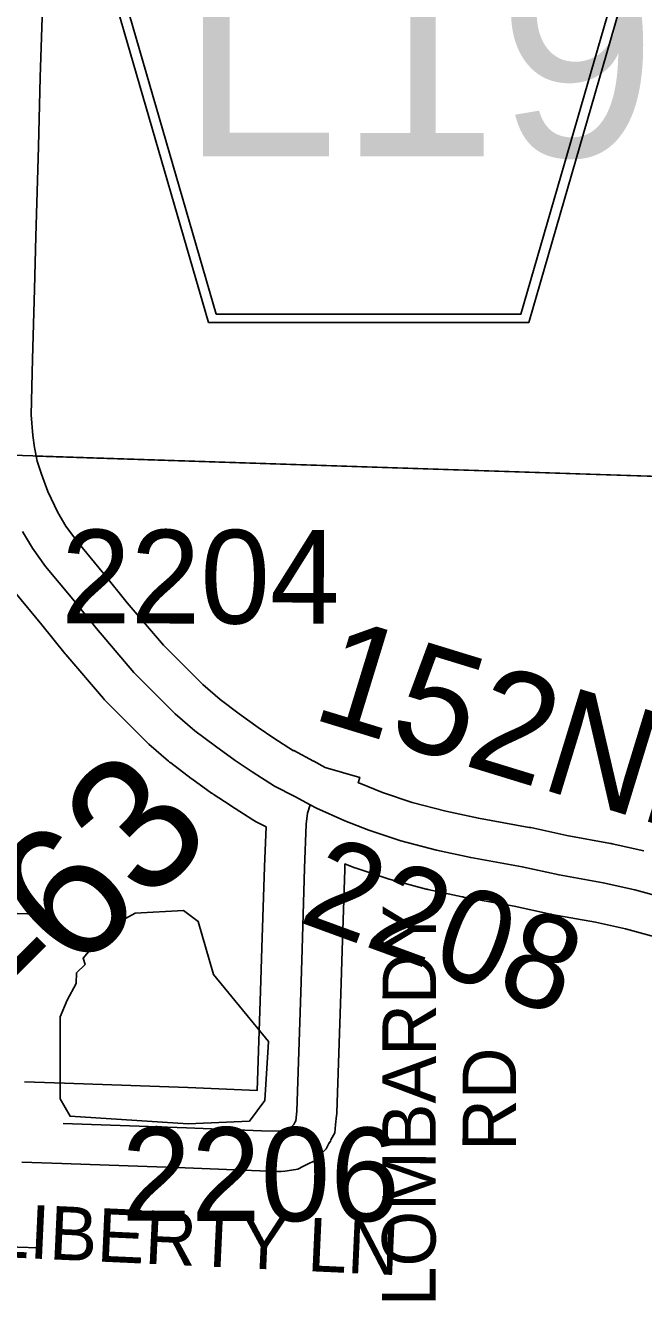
# Model space of a CAD drawing. Extents: x -132.8 to -73.3, y -60 to -26.
# Drawn here: x -124.572 to -124.11, y -41.902 to -40.948 of the extents above; entities that cross this region are included whole.
import ezdxf

# ---------------------------------------------------------------- set-up
doc = ezdxf.new("R2010")
doc.units = 0
for name, color, linetype in [('tdCoHydroRiver', 7, 'Continuous'), ('tdCoRRCL', 7, 'Continuous'), ('tdCoSecRdNmbr', 7, 'Continuous'), ('tdCoSecRdTxt', 7, 'Continuous'), ('tdCoSecRteBand', 7, 'Continuous'), ('tdCoSecRteCL', 7, 'Continuous'), ('tdCoSectLine', 7, 'Continuous'), ('tdCoSectLinePart', 7, 'Continuous'), ('tdCoShieldCoRte', 7, 'Continuous'), ('tdCoSurfEarth', 7, 'Continuous'), ('tdCoSurfGravel', 7, 'Continuous'), ('tdStHwyIntRefPost1', 7, 'Continuous')]:
    doc.layers.add(name, color=color, linetype=linetype)

msp = doc.modelspace()

# ---------------------------------------------------------------- linework, layer by layer
at = {"layer": 'tdCoHydroRiver'}
msp.add_lwpolyline([(-124.45016, -41.76951), (-124.53839, -41.76384), (-124.54591, -41.751), (-124.54574, -41.68948), (-124.54065, -41.677), (-124.53399, -41.66457), (-124.53376, -41.65669), (-124.52727, -41.65056), (-124.52871, -41.64579), (-124.50912, -41.62268), (-124.48988, -41.61219), (-124.45352, -41.61007), (-124.44271, -41.61827), (-124.43121, -41.65804), (-124.39002, -41.70812), (-124.39285, -41.75221), (-124.40434, -41.76766), (-124.45016, -41.76951)], dxfattribs=at)
at = {"layer": 'tdCoRRCL'}
for p, q in [((-124.63015, -41.61051), (-124.5552, -41.61314)), ((-124.63668, -41.8601), (-124.56171, -41.86228))]:
    msp.add_line(p, q, dxfattribs=at)
at = {"layer": 'tdCoSecRteBand'}
for points in [[(-124.55888, -40.92716), (-124.56075, -40.98745), (-124.56195, -41.03885), (-124.56195, -41.03897), (-124.56195, -41.03909), (-124.56405, -41.1063), (-124.56507, -41.14565), (-124.56507, -41.14568), (-124.56507, -41.14571), (-124.56651, -41.1979), (-124.56747, -41.23951), (-124.56632, -41.25503), (-124.56504, -41.26406), (-124.56305, -41.27412), (-124.55975, -41.28384), (-124.5551, -41.2969), (-124.54764, -41.31245), (-124.54155, -41.32268), (-124.53298, -41.33454), (-124.51327, -41.35831), (-124.51315, -41.35846), (-124.51302, -41.35862), (-124.49566, -41.38014), (-124.46868, -41.41178), (-124.43928, -41.44109), (-124.42626, -41.45244), (-124.412, -41.46313), (-124.39789, -41.47336), (-124.38601, -41.48119), (-124.37125, -41.49062), (-124.37116, -41.49045), (-124.35644, -41.49838), (-124.35644, -41.49838), (-124.35622, -41.4985), (-124.34756, -41.50317), (-124.3218, -41.51063), (-124.32294, -41.51456), (-124.32137, -41.51524), (-124.30482, -41.5218), (-124.28258, -41.52923), (-124.25753, -41.53581), (-124.23302, -41.54109), (-124.19504, -41.54794), (-124.19451, -41.54804), (-124.19398, -41.54815), (-124.16686, -41.55405), (-124.13433, -41.55994), (-124.13372, -41.56005), (-124.13312, -41.56018), (-124.10944, -41.56547)], [(-124.57249, -41.73823), (-124.5425, -41.73927), (-124.45027, -41.74248), (-124.4502, -41.74248), (-124.45013, -41.74248), (-124.39845, -41.74453), (-124.39597, -41.67037), (-124.39494, -41.63796), (-124.39301, -41.57742), (-124.39301, -41.57734), (-124.39301, -41.57725), (-124.39189, -41.54759), (-124.39931, -41.54375), (-124.40053, -41.54312), (-124.40168, -41.54238), (-124.4185, -41.53163), (-124.41867, -41.53152), (-124.41884, -41.53141), (-124.43146, -41.5231), (-124.43202, -41.52273), (-124.43256, -41.52233), (-124.44741, -41.51157), (-124.4476, -41.51143), (-124.44779, -41.51129), (-124.46313, -41.49979), (-124.46402, -41.49912), (-124.46485, -41.4984), (-124.47946, -41.48566), (-124.48022, -41.485), (-124.48093, -41.48429), (-124.51191, -41.45341), (-124.51277, -41.45255), (-124.51355, -41.45163), (-124.54158, -41.41876), (-124.54185, -41.41844), (-124.5421, -41.41813), (-124.55959, -41.39645), (-124.5798, -41.37207)], [(-124.10109, -41.62973), (-124.1231, -41.6239), (-124.14561, -41.61887), (-124.17807, -41.613), (-124.17858, -41.6129), (-124.1791, -41.61279), (-124.20621, -41.60689), (-124.24416, -41.60005), (-124.24466, -41.59996), (-124.24516, -41.59986), (-124.27082, -41.59433), (-124.27148, -41.59419), (-124.27212, -41.59402), (-124.29878, -41.58701), (-124.29973, -41.58676), (-124.30066, -41.58645), (-124.32461, -41.57845), (-124.3254, -41.57819), (-124.32616, -41.57788), (-124.33289, -41.57522), (-124.33305, -41.57942), (-124.33497, -41.63987), (-124.336, -41.6723), (-124.336, -41.67233), (-124.33601, -41.67235), (-124.33897, -41.76113), (-124.339, -41.76217), (-124.33911, -41.76322), (-124.33985, -41.77037), (-124.34047, -41.77636), (-124.34335, -41.78165), (-124.34377, -41.78241), (-124.34483, -41.78436), (-124.3469, -41.78815), (-124.34995, -41.79121), (-124.35267, -41.79392), (-124.35611, -41.79736), (-124.36046, -41.79954), (-124.36392, -41.80126), (-124.36817, -41.80339), (-124.37288, -41.8041), (-124.37781, -41.80484), (-124.38059, -41.80526), (-124.3834, -41.80515), (-124.39647, -41.80466), (-124.3965, -41.80466), (-124.39652, -41.80465), (-124.45243, -41.80244), (-124.54459, -41.79923), (-124.57457, -41.79819)]]:
    msp.add_lwpolyline(points, dxfattribs=at)
at = {"layer": 'tdCoSecRteCL'}
for points in [[(-124.35897, -41.53109), (-124.37045, -41.52491), (-124.38552, -41.51711), (-124.40234, -41.50636), (-124.41495, -41.49804), (-124.4298, -41.48728), (-124.44514, -41.47578), (-124.45975, -41.46305), (-124.49072, -41.43216), (-124.51875, -41.39929), (-124.53637, -41.37745), (-124.55671, -41.35292), (-124.56664, -41.33917), (-124.5741, -41.32664)], [(-124.54355, -41.76925), (-124.45132, -41.77246), (-124.39534, -41.77468), (-124.38227, -41.77517), (-124.37733, -41.77443), (-124.37388, -41.77271), (-124.37117, -41.76999), (-124.37011, -41.76805), (-124.36969, -41.76728), (-124.36895, -41.76013), (-124.36599, -41.67135), (-124.36496, -41.63892), (-124.36303, -41.57838), (-124.3618, -41.54558), (-124.36081, -41.53744), (-124.35897, -41.53109)], [(-124.09229, -41.60103), (-124.11598, -41.59475), (-124.13967, -41.58946), (-124.17272, -41.58348), (-124.20036, -41.57747), (-124.23884, -41.57053), (-124.2645, -41.565), (-124.29116, -41.558), (-124.31511, -41.55), (-124.33289, -41.54295), (-124.35413, -41.5337), (-124.35897, -41.53109)]]:
    msp.add_lwpolyline(points, dxfattribs=at)
at = {"layer": 'tdCoSectLine'}
msp.add_lwpolyline([(-124.61958, -41.26852), (-123.619, -41.30129)], dxfattribs=at)
at = {"layer": 'tdCoSectLinePart'}
msp.add_lwpolyline([(-124.56409, -41.27033), (-123.619, -41.30129)], dxfattribs=at)
at = {"layer": 'tdCoShieldCoRte'}
for points in [[(-124.43497, -41.17057), (-124.51691, -40.88768), (-124.52079, -40.87452), (-124.52151, -40.86864), (-124.52151, -40.86081), (-124.51727, -40.8505), (-124.51, -40.84201), (-124.50042, -40.83534), (-124.33315, -40.763), (-124.32563, -40.76136), (-124.31521, -40.76045), (-124.30478, -40.76136), (-124.29727, -40.763), (-124.12999, -40.83534), (-124.12041, -40.84201), (-124.11314, -40.8505), (-124.1089, -40.86081), (-124.1089, -40.86864), (-124.10963, -40.87452), (-124.1135, -40.88768), (-124.19545, -41.17057)], [(-124.42911, -41.16424), (-124.50884, -40.88897), (-124.51256, -40.87634), (-124.51326, -40.87069), (-124.51326, -40.86318), (-124.50919, -40.85328), (-124.50221, -40.84513), (-124.49301, -40.83873), (-124.33243, -40.76927), (-124.32521, -40.7677), (-124.31521, -40.76683), (-124.3052, -40.7677), (-124.29798, -40.76927), (-124.1374, -40.83873), (-124.1282, -40.84513), (-124.12122, -40.85328), (-124.11715, -40.86318), (-124.11715, -40.87069), (-124.11785, -40.87634), (-124.12157, -40.88897), (-124.20131, -41.16424)]]:
    msp.add_lwpolyline(points, close=True, dxfattribs=at)
at = {"layer": 'tdCoSurfEarth'}
msp.add_lwpolyline([(-124.54355, -41.76925), (-124.45132, -41.77246), (-124.39534, -41.77468), (-124.38227, -41.77517), (-124.37733, -41.77443), (-124.37388, -41.77271), (-124.37117, -41.76999), (-124.37011, -41.76805), (-124.36969, -41.76728), (-124.36895, -41.76013), (-124.36599, -41.67135), (-124.36496, -41.63892)], dxfattribs=at)
at = {"layer": 'tdCoSurfGravel'}
for points in [[(-124.09229, -41.60103), (-124.11598, -41.59475), (-124.13967, -41.58946), (-124.17272, -41.58348), (-124.20036, -41.57747), (-124.23884, -41.57053), (-124.2645, -41.565), (-124.29116, -41.558), (-124.31511, -41.55), (-124.33289, -41.54295), (-124.35413, -41.5337), (-124.35897, -41.53109), (-124.37045, -41.52491), (-124.38552, -41.51711), (-124.40234, -41.50636), (-124.41495, -41.49804), (-124.4298, -41.48728), (-124.44514, -41.47578), (-124.45975, -41.46305), (-124.49072, -41.43216), (-124.51875, -41.39929), (-124.53637, -41.37745), (-124.55671, -41.35292), (-124.56664, -41.33917), (-124.5741, -41.32664)], [(-124.36496, -41.63892), (-124.36303, -41.57838), (-124.3618, -41.54558), (-124.36081, -41.53744), (-124.35897, -41.53109)]]:
    msp.add_lwpolyline(points, dxfattribs=at)

# ---------------------------------------------------------------- texts
at = {"layer": 'tdCoSecRdNmbr'}
for s, rotation, p in [('2204', 359.90686, (-124.54517, -41.3954)), ('2208', 339.90695, (-124.36867, -41.61818)), ('2206', 359.90679, (-124.5001, -41.84204))]:
    msp.add_text(s, height=0.07, rotation=rotation, dxfattribs=at).set_placement(p)
at = {"layer": 'tdCoSecRdTxt'}
for s, height, rotation, p in [('152ND ST', 0.08, 342.96103, (-124.35923, -41.46616)), ('LOMBARDY', 0.04, 89.90963, (-124.26516, -41.90602)), ('RD', 0.04, 89.90963, (-124.20498, -41.78983)), ('LIBERTY LN', 0.04, 357.37535, (-124.59912, -41.86874))]:
    msp.add_text(s, height=height, rotation=rotation, dxfattribs=at).set_placement(p)
at = {"layer": 'tdCoShieldCoRte'}
msp.add_text('L19', height=0.16, dxfattribs=at).set_placement((-124.45669, -41.04631))
at = {"layer": 'tdStHwyIntRefPost1'}
msp.add_text('‒‒63', height=0.1, rotation=45, dxfattribs=at).set_placement((-124.63889, -41.76435))

doc.saveas('drawing.dxf')
